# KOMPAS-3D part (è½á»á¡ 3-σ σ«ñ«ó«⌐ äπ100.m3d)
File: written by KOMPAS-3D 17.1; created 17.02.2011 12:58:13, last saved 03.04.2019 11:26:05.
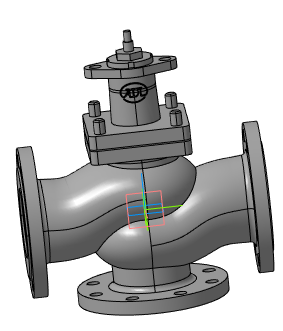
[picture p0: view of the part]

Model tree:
1. Плоскость XY
2. Плоскость ZX
3. Плоскость ZY
4. Ось X
5. Ось Y
6. Ось Z
7. Начало координат
8. Операция без истории:2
